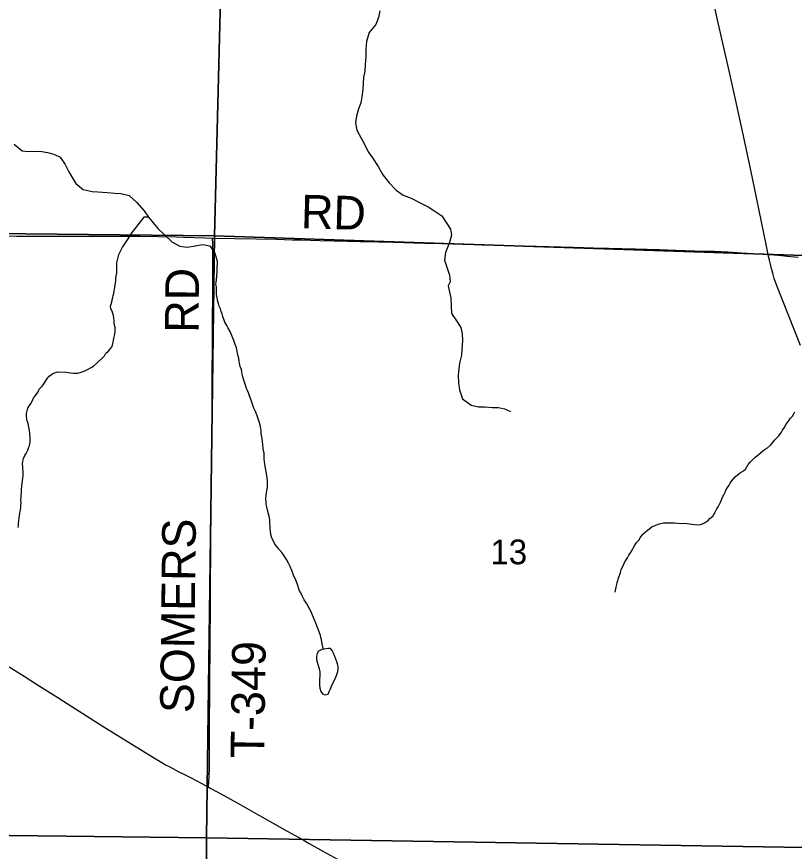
# Model space of a CAD drawing. Extents: x -8.8 to 41.4, y 0 to 34.6.
# Drawn here: x -6.769 to -5.453, y 15.544 to 16.957 of the extents above; entities that cross this region are included whole.
import ezdxf

# ---------------------------------------------------------------- set-up
doc = ezdxf.new("R2010")
doc.units = 0
for name, color, linetype in [('GM_X_Corporation', 7, 'Continuous'), ('GM_X_County_Road', 7, 'Continuous'), ('GM_X_Minor_Lake', 7, 'Continuous'), ('GM_X_Minor_River', 7, 'Continuous'), ('GM_X_Section_Text', 7, 'Continuous'), ('GM_X_Township_Road', 7, 'Continuous'), ('GM_X_Township_Road_Text', 7, 'Continuous'), ('GM_X_Township_Text', 7, 'Continuous')]:
    doc.layers.add(name, color=color, linetype=linetype)

msp = doc.modelspace()

# ---------------------------------------------------------------- linework, layer by layer
at = {"layer": 'GM_X_Corporation'}
for points in [[(-7.4378, 17.5869), (-6.4092, 17.5696), (-6.4339, 16.586), (-7.4474, 16.5968)], [(-5.4036, 17.5614), (-5.4203, 16.5519), (-6.4339, 16.586), (-6.4092, 17.5696)], [(-7.4474, 16.5968), (-6.4339, 16.586), (-6.4479, 15.5667), (-7.4468, 15.5783)], [(-6.4339, 16.586), (-5.4203, 16.5519), (-5.4349, 15.5503), (-6.4479, 15.5667)], [(-6.4479, 15.5667), (-6.4506, 14.5538), (-7.4475, 14.5649), (-7.4468, 15.5783)], [(-6.4479, 15.5667), (-5.4349, 15.5503), (-5.4351, 15.4586), (-5.4406, 14.5401), (-6.4506, 14.5538)]]:
    msp.add_lwpolyline(points, close=True, dxfattribs=at)
at = {"layer": 'GM_X_County_Road'}
for points in [[(-5.4423, 16.4001), (-5.4831, 16.5029), (-5.4868, 16.5136), (-5.4887, 16.5202), (-5.4904, 16.5266), (-5.4919, 16.5325), (-5.4932, 16.5379), (-5.4948, 16.5447), (-5.4963, 16.5511), (-5.497, 16.5543), (-5.4998, 16.5684), (-5.5165, 16.6509), (-5.5261, 16.6973), (-5.5371, 16.7472), (-5.5507, 16.8095), (-5.563, 16.8654), (-5.5814, 16.9466), (-5.603, 17.0446)], [(-6.8324, 16.5857), (-6.7685, 16.5853), (-6.7417, 16.5853), (-6.7064, 16.5854), (-6.6685, 16.5853), (-6.6437, 16.5853), (-6.6182, 16.5853), (-6.6049, 16.5854), (-6.5897, 16.5853), (-6.5599, 16.5851), (-6.4984, 16.5841), (-6.4866, 16.5837), (-6.45, 16.5825), (-6.4374, 16.5822), (-6.3996, 16.5815), (-6.363, 16.5808), (-6.3289, 16.58), (-6.3022, 16.5793), (-6.2873, 16.5791), (-6.2562, 16.578), (-6.2096, 16.577), (-6.1873, 16.5765), (-6.1568, 16.5757), (-6.1314, 16.575), (-6.0966, 16.5741), (-6.078, 16.5737), (-6.0501, 16.5728), (-6.0314, 16.5722), (-6.014, 16.5718), (-5.9911, 16.5711), (-5.9817, 16.5709), (-5.9563, 16.5703), (-5.9097, 16.5688), (-5.8687, 16.5677), (-5.8265, 16.5667), (-5.7929, 16.5658), (-5.7675, 16.5651), (-5.7215, 16.5637), (-5.6812, 16.5625), (-5.6532, 16.5617), (-5.6209, 16.5606), (-5.6059, 16.5601), (-5.588, 16.5598), (-5.577, 16.5594), (-5.5651, 16.5589), (-5.5423, 16.5574), (-5.5158, 16.5557), (-5.497, 16.5543), (-5.4876, 16.5537), (-5.4746, 16.5526), (-5.4647, 16.5517), (-5.4463, 16.55)], [(-6.7889, 15.8609), (-6.7563, 15.8403), (-6.7354, 15.8269), (-6.6992, 15.804), (-6.6756, 15.7889), (-6.6567, 15.7769), (-6.6241, 15.7564), (-6.5741, 15.7251), (-6.5567, 15.7142), (-6.5404, 15.7041), (-6.5233, 15.6941), (-6.5168, 15.6904), (-6.5097, 15.6866), (-6.4943, 15.6785), (-6.486, 15.6743), (-6.4738, 15.668), (-6.465, 15.6634), (-6.4568, 15.6591), (-6.444, 15.6523), (-6.4414, 15.6509), (-6.4283, 15.6438), (-6.3909, 15.6228), (-6.3671, 15.6094), (-6.3362, 15.592), (-6.3113, 15.578), (-6.2842, 15.5629), (-6.2738, 15.5572), (-6.2505, 15.5442), (-6.2195, 15.527)]]:
    msp.add_lwpolyline(points, dxfattribs=at)
at = {"layer": 'GM_X_Minor_Lake'}
for points in [[(-6.238, 15.8871), (-6.2412, 15.8874), (-6.2457, 15.8868), (-6.2495, 15.8861), (-6.2534, 15.8851), (-6.258, 15.8826), (-6.2604, 15.8785), (-6.2613, 15.8739), (-6.2614, 15.8698), (-6.2607, 15.8656), (-6.258, 15.8564), (-6.2569, 15.8525), (-6.2559, 15.8476), (-6.2557, 15.8434), (-6.2558, 15.8396), (-6.2563, 15.8358), (-6.2566, 15.8248), (-6.2556, 15.8202), (-6.2539, 15.8141), (-6.2513, 15.8102), (-6.2468, 15.8086), (-6.2418, 15.8099), (-6.2398, 15.8141), (-6.2386, 15.8178), (-6.2366, 15.8219), (-6.2349, 15.8261), (-6.2309, 15.8336), (-6.2289, 15.8384), (-6.2272, 15.843), (-6.2256, 15.8482), (-6.2247, 15.8531), (-6.2246, 15.8569), (-6.2259, 15.8614), (-6.2296, 15.8727)], [(-6.2296, 15.8727), (-6.2309, 15.875), (-6.2327, 15.8792), (-6.2352, 15.8835), (-6.238, 15.8871)]]:
    msp.add_lwpolyline(points, dxfattribs=at)
at = {"layer": 'GM_X_Minor_River'}
for points in [[(-6.1542, 16.9668), (-6.1564, 16.9554), (-6.1609, 16.9438), (-6.1726, 16.93), (-6.1767, 16.915), (-6.1782, 16.9017), (-6.1781, 16.8896), (-6.1792, 16.8756), (-6.1799, 16.8646), (-6.1817, 16.854), (-6.1823, 16.8446)], [(-6.1823, 16.8446), (-6.1829, 16.8336), (-6.1848, 16.8215), (-6.1865, 16.8109), (-6.1902, 16.8008), (-6.1939, 16.7883), (-6.1953, 16.777), (-6.193, 16.7648), (-6.1861, 16.7514), (-6.1803, 16.741), (-6.1738, 16.7279), (-6.1665, 16.7179), (-6.157, 16.7036), (-6.149, 16.6894), (-6.1383, 16.6759), (-6.1269, 16.6631), (-6.1149, 16.6548), (-6.101, 16.6495), (-6.0838, 16.6408), (-6.0726, 16.6352), (-6.0629, 16.6289), (-6.0494, 16.6198), (-6.0407, 16.6067), (-6.0345, 16.5971), (-6.0328, 16.5872), (-6.0361, 16.5747), (-6.0434, 16.5579), (-6.0449, 16.5446), (-6.041, 16.5328), (-6.0364, 16.5194), (-6.0352, 16.508)], [(-6.7732, 16.7411), (-6.7594, 16.7301), (-6.7496, 16.7288), (-6.7389, 16.7293), (-6.7264, 16.7286), (-6.7166, 16.7272), (-6.7061, 16.7243), (-6.6956, 16.7191), (-6.6871, 16.7067), (-6.6806, 16.6945), (-6.6752, 16.6848), (-6.669, 16.6748), (-6.6563, 16.6643), (-6.6413, 16.6609), (-6.6314, 16.6603), (-6.6159, 16.6595), (-6.6026, 16.6584), (-6.5924, 16.6578), (-6.5788, 16.654), (-6.5655, 16.6423), (-6.5529, 16.6284), (-6.5456, 16.6176), (-6.5379, 16.6079), (-6.5298, 16.5982), (-6.5194, 16.5881), (-6.5064, 16.576), (-6.493, 16.5685), (-6.4801, 16.5667), (-6.466, 16.569), (-6.4542, 16.571), (-6.4421, 16.5691), (-6.4333, 16.5568), (-6.4295, 16.543), (-6.4305, 16.5148)], [(-6.5456, 16.6176), (-6.554, 16.6174), (-6.5641, 16.6047), (-6.5743, 16.5917), (-6.5822, 16.579), (-6.5901, 16.5671), (-6.5965, 16.554), (-6.5999, 16.54), (-6.5999, 16.5218)], [(-6.6014, 16.5097), (-6.6009, 16.5135), (-6.5999, 16.5218)], [(-6.7665, 16.0918), (-6.7661, 16.0956), (-6.766, 16.099), (-6.7651, 16.1039), (-6.7646, 16.1085), (-6.7641, 16.1119), (-6.7636, 16.1168), (-6.7627, 16.1214), (-6.7621, 16.1263), (-6.7617, 16.1297), (-6.7616, 16.1339), (-6.7618, 16.1381), (-6.7613, 16.1434), (-6.761, 16.1532), (-6.7609, 16.1566), (-6.76, 16.1623), (-6.7585, 16.176), (-6.758, 16.1794), (-6.7578, 16.1877), (-6.7584, 16.1919), (-6.7587, 16.1953), (-6.7589, 16.1995), (-6.7588, 16.2041), (-6.7575, 16.2086), (-6.7551, 16.2139), (-6.7527, 16.2176), (-6.7503, 16.2232), (-6.7487, 16.227), (-6.7474, 16.2304), (-6.7466, 16.2338), (-6.7461, 16.2379), (-6.7463, 16.2421), (-6.7468, 16.252), (-6.7471, 16.2562), (-6.7481, 16.2619), (-6.7494, 16.2684), (-6.7512, 16.2726), (-6.7518, 16.2761), (-6.7525, 16.2803), (-6.7523, 16.2848), (-6.7514, 16.2894), (-6.7498, 16.2939), (-6.747, 16.2984), (-6.7446, 16.3025), (-6.743, 16.3059), (-6.7402, 16.3111), (-6.737, 16.3156), (-6.7327, 16.3215), (-6.7307, 16.326), (-6.7252, 16.3319), (-6.7169, 16.345), (-6.7137, 16.3483), (-6.7102, 16.3513), (-6.7068, 16.3531), (-6.7029, 16.3545), (-6.6991, 16.3555), (-6.6851, 16.3551), (-6.6817, 16.3547), (-6.6775, 16.3542), (-6.6726, 16.3533), (-6.6692, 16.3532), (-6.6654, 16.3534), (-6.6616, 16.3545), (-6.6581, 16.3555), (-6.6535, 16.3573), (-6.6489, 16.3598), (-6.6431, 16.3631), (-6.6381, 16.3656), (-6.6241, 16.3789), (-6.6202, 16.3829), (-6.6178, 16.3871), (-6.6135, 16.3907), (-6.61, 16.3952), (-6.6076, 16.3986), (-6.6059, 16.4061), (-6.605, 16.4095), (-6.6037, 16.4148), (-6.6028, 16.4193), (-6.6023, 16.4231), (-6.6022, 16.4265), (-6.6025, 16.4307), (-6.6035, 16.4349), (-6.6038, 16.4387), (-6.6041, 16.4421), (-6.6043, 16.4467), (-6.605, 16.4509), (-6.6064, 16.4544), (-6.6074, 16.4586), (-6.6096, 16.4624), (-6.6102, 16.4666), (-6.609, 16.4704), (-6.6081, 16.4738), (-6.6072, 16.4776), (-6.606, 16.4817), (-6.6055, 16.4851), (-6.6047, 16.4885), (-6.6042, 16.4923), (-6.6033, 16.4957), (-6.6028, 16.4991), (-6.6023, 16.5029), (-6.6014, 16.5097)], [(-6.4134, 16.4341), (-6.4167, 16.4399), (-6.4202, 16.4491), (-6.4212, 16.4537), (-6.4226, 16.4576), (-6.424, 16.4622), (-6.4262, 16.4668), (-6.4276, 16.4714), (-6.4289, 16.4767), (-6.4296, 16.4813), (-6.4305, 16.4867), (-6.4308, 16.4927), (-6.4307, 16.4962), (-6.4309, 16.4996), (-6.4316, 16.5038), (-6.4315, 16.5076), (-6.431, 16.5114), (-6.4305, 16.5148)], [(-6.0352, 16.508), (-6.0385, 16.5011), (-6.0366, 16.4908), (-6.0342, 16.4808), (-6.0335, 16.4675), (-6.0331, 16.4542), (-6.0254, 16.4437), (-6.0171, 16.4309), (-6.0148, 16.4199), (-6.0144, 16.4085), (-6.0152, 16.3933), (-6.0159, 16.3838), (-6.0193, 16.3703), (-6.0204, 16.36), (-6.0218, 16.3502), (-6.0214, 16.3365), (-6.0195, 16.3251), (-6.0143, 16.3097), (-5.9998, 16.299), (-5.9874, 16.2964), (-5.9764, 16.2961), (-5.9635, 16.2953), (-5.9532, 16.2954), (-5.9434, 16.2932), (-5.9333, 16.2883)], [(-6.2495, 15.8861), (-6.2513, 15.8919), (-6.2516, 15.8953), (-6.2529, 15.9022), (-6.2539, 15.9056), (-6.2546, 15.9091), (-6.2567, 15.9152), (-6.2595, 15.9225), (-6.2627, 15.9302), (-6.2656, 15.9368), (-6.268, 15.9437), (-6.2712, 15.9502), (-6.2745, 15.9564), (-6.2781, 15.9629), (-6.2821, 15.9695), (-6.2853, 15.9753), (-6.2882, 15.9815), (-6.2907, 15.9861), (-6.2931, 15.9938), (-6.2942, 15.9972), (-6.2967, 16.0026), (-6.3002, 16.0111), (-6.3031, 16.0191), (-6.3063, 16.0261), (-6.3091, 16.0318), (-6.3124, 16.038), (-6.316, 16.0438), (-6.32, 16.0496), (-6.3252, 16.0551), (-6.3288, 16.0597), (-6.3318, 16.0636), (-6.3339, 16.0675), (-6.3357, 16.0717), (-6.3379, 16.0763), (-6.3385, 16.0802), (-6.3395, 16.0855), (-6.3398, 16.0897), (-6.34, 16.0931), (-6.3402, 16.1), (-6.3404, 16.1053), (-6.3414, 16.1106), (-6.3442, 16.1214), (-6.3455, 16.1271), (-6.3465, 16.1313), (-6.3468, 16.1347), (-6.347, 16.1404), (-6.3465, 16.1473), (-6.346, 16.1507), (-6.3455, 16.1544), (-6.3446, 16.1605), (-6.3444, 16.1658), (-6.3446, 16.1715), (-6.3449, 16.1753), (-6.3456, 16.1788), (-6.3462, 16.1833), (-6.3475, 16.1898), (-6.3488, 16.199), (-6.3494, 16.204), (-6.35, 16.2085), (-6.3499, 16.2131), (-6.3502, 16.2177), (-6.3515, 16.2253), (-6.3524, 16.2333), (-6.353, 16.2371), (-6.3536, 16.2425), (-6.3549, 16.2505), (-6.3551, 16.2573), (-6.3561, 16.2619), (-6.3568, 16.2661), (-6.3588, 16.2726), (-6.3613, 16.2795), (-6.3641, 16.2872), (-6.3659, 16.2907), (-6.3673, 16.2941), (-6.3684, 16.2976), (-6.3708, 16.3041), (-6.373, 16.3103), (-6.3754, 16.3168), (-6.3768, 16.3202), (-6.3783, 16.3241), (-6.3797, 16.3275), (-6.3814, 16.3333), (-6.3839, 16.3398), (-6.3866, 16.349), (-6.388, 16.3555), (-6.3886, 16.3593), (-6.3908, 16.3647), (-6.3917, 16.3704), (-6.3924, 16.3739), (-6.393, 16.3788), (-6.3941, 16.3823), (-6.395, 16.3872), (-6.3957, 16.3907), (-6.3971, 16.396), (-6.3992, 16.4018), (-6.4013, 16.4087), (-6.4031, 16.4125), (-6.4052, 16.4183), (-6.4077, 16.4237), (-6.4113, 16.4306), (-6.4134, 16.4341)], [(-5.7562, 15.9824), (-5.7545, 15.9908), (-5.7532, 15.9957), (-5.7523, 15.9991), (-5.7498, 16.0081), (-5.7482, 16.0122), (-5.7469, 16.016), (-5.7457, 16.0201), (-5.744, 16.0243), (-5.742, 16.0284), (-5.74, 16.0329), (-5.7372, 16.0374), (-5.7352, 16.0407), (-5.7328, 16.0452), (-5.73, 16.0493), (-5.7272, 16.0538), (-5.7248, 16.0579), (-5.7224, 16.0624), (-5.7201, 16.0665), (-5.7161, 16.0706), (-5.7137, 16.0747), (-5.709, 16.0807), (-5.7051, 16.0844), (-5.7012, 16.0877), (-5.697, 16.0906), (-5.6931, 16.0935), (-5.6885, 16.0957), (-5.6831, 16.0974), (-5.6785, 16.0988), (-5.674, 16.0998), (-5.6705, 16.1001), (-5.6557, 16.0997), (-5.6504, 16.0992), (-5.6349, 16.0987), (-5.6304, 16.0982), (-5.6262, 16.0977), (-5.616, 16.0963), (-5.6114, 16.0969), (-5.608, 16.098), (-5.6034, 16.1005), (-5.5987, 16.1038), (-5.5956, 16.1071), (-5.5909, 16.1115), (-5.5861, 16.119), (-5.5837, 16.1235), (-5.5817, 16.1269), (-5.5777, 16.1351), (-5.5757, 16.1389), (-5.5741, 16.1434), (-5.5717, 16.1482), (-5.57, 16.152), (-5.568, 16.1565), (-5.5656, 16.1598), (-5.5632, 16.164), (-5.5612, 16.1673), (-5.5589, 16.1707), (-5.5522, 16.1785), (-5.546, 16.1832), (-5.5425, 16.1858), (-5.5387, 16.188), (-5.5352, 16.1909), (-5.5331, 16.195), (-5.5308, 16.1988), (-5.5276, 16.2029), (-5.5233, 16.2069), (-5.519, 16.211), (-5.5144, 16.2143), (-5.5105, 16.2179), (-5.5058, 16.2216), (-5.502, 16.2245), (-5.4981, 16.2271), (-5.493, 16.2315), (-5.4891, 16.236), (-5.4863, 16.2397), (-5.4824, 16.2438), (-5.4789, 16.2475), (-5.4746, 16.2534), (-5.4726, 16.2568), (-5.4698, 16.2609), (-5.467, 16.2657), (-5.4646, 16.2695), (-5.4615, 16.2736), (-5.4591, 16.2773), (-5.456, 16.2806), (-5.4536, 16.2844), (-5.4516, 16.2881)]]:
    msp.add_lwpolyline(points, dxfattribs=at)
at = {"layer": 'GM_X_Township_Road'}
msp.add_lwpolyline([(-6.444, 15.6523), (-6.4435, 15.6616), (-6.443, 15.6704), (-6.4427, 15.684), (-6.4425, 15.7089), (-6.4425, 15.7592), (-6.4424, 15.7772), (-6.4422, 15.7946), (-6.442, 15.8145), (-6.4419, 15.8312), (-6.4418, 15.8523), (-6.4417, 15.8691), (-6.4414, 15.9033), (-6.441, 15.9548), (-6.441, 15.9654), (-6.4409, 15.9797), (-6.4408, 16.0113), (-6.4405, 16.0349), (-6.4403, 16.0616), (-6.4402, 16.0809), (-6.44, 16.1076), (-6.4397, 16.1362), (-6.4395, 16.1486), (-6.4392, 16.1939), (-6.4386, 16.2393), (-6.4383, 16.2766), (-6.4382, 16.3058), (-6.438, 16.3306), (-6.4378, 16.3498), (-6.4375, 16.4002), (-6.4375, 16.407), (-6.4374, 16.4262), (-6.4373, 16.4417), (-6.4368, 16.4889), (-6.4367, 16.5094), (-6.4368, 16.5377), (-6.4369, 16.5551), (-6.4372, 16.5725), (-6.4374, 16.5822)], dxfattribs=at)

# ---------------------------------------------------------------- texts
at = {"layer": 'GM_X_Section_Text'}
for s, rotation, p in [('RD', 89.5059, (-6.4612, 16.4216)), ('SOMERS', 89.3118, (-6.4695, 15.7775)), ('T-349', 89.1574, (-6.3502, 15.7008))]:
    msp.add_text(s, height=0.05682, rotation=rotation, dxfattribs=at).set_placement(p)
at = {"layer": 'GM_X_Township_Road_Text'}
msp.add_text('RD', height=0.05682, rotation=358.5184, dxfattribs=at).set_placement((-6.2883, 16.5988))
at = {"layer": 'GM_X_Township_Text'}
msp.add_text('13', height=0.04186, rotation=0, dxfattribs=at).set_placement((-5.9672, 16.0298))

doc.saveas('drawing.dxf')
